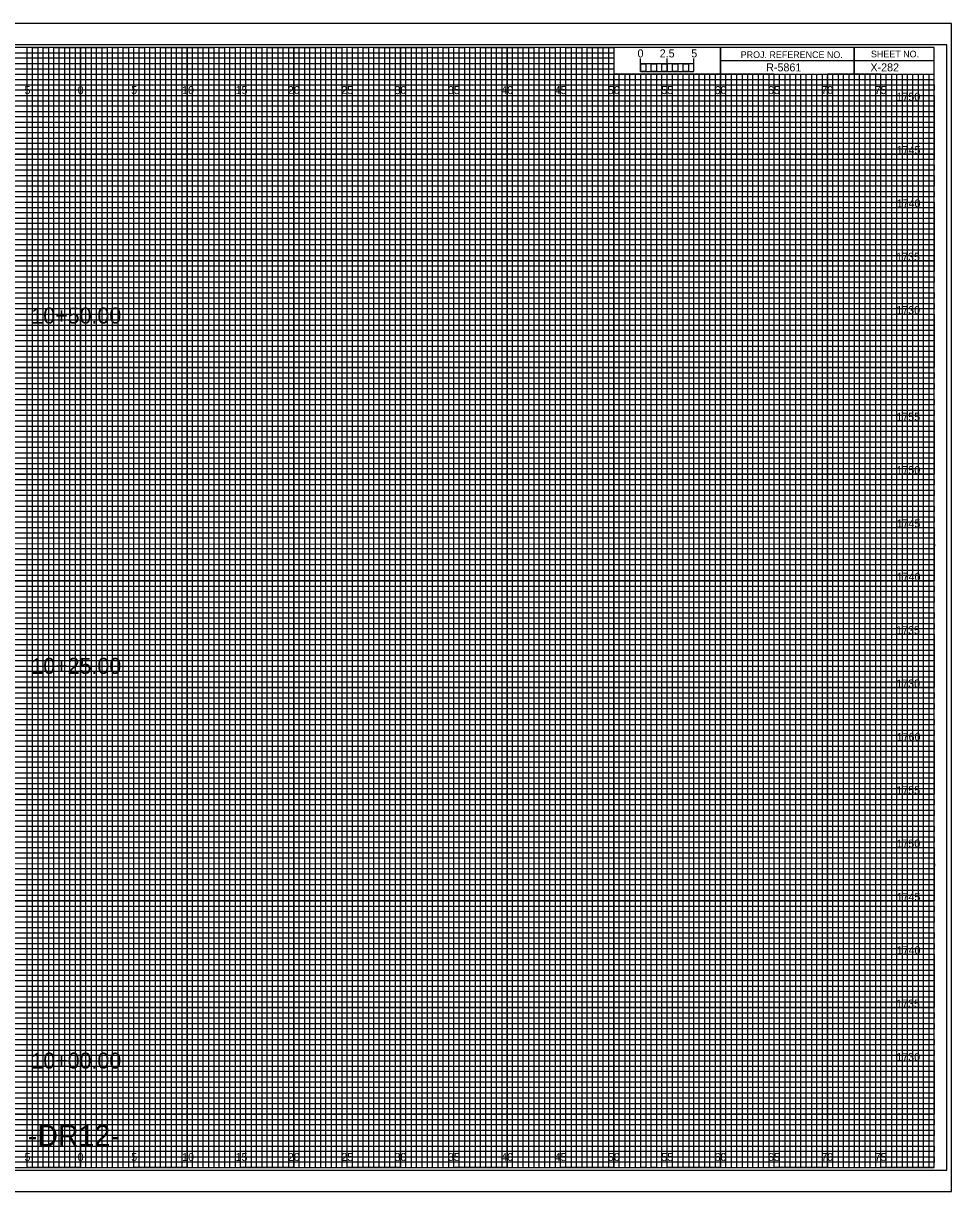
# Model space of a CAD drawing. Extents: x -7 to 162, y -2 to 327.
# Drawn here: x 74.6 to 161.7, y -2.3 to 107.3 of the extents above; entities that cross this region are included whole.
import ezdxf

# ---------------------------------------------------------------- set-up
doc = ezdxf.new("R2010")
doc.units = 0
for name, color, linetype in [('Prop XS Alignment Label', 7, 'Continuous'), ('Prop XS Bar Scale Labels', 7, 'Continuous'), ('Prop XS Elevation Labels', 7, 'Continuous'), ('Prop XS Offset Labels', 7, 'Continuous'), ('Prop XS Project Number', 7, 'Continuous'), ('Prop XS Sheet Number', 7, 'Continuous'), ('Prop XS Station Labels', 7, 'Continuous'), ('Sheet Cross Section CELL', 7, 'Continuous'), ('Sheet Cross Section Grid Major CELL', 7, 'Continuous'), ('Sheet Cross Section Grid Middle CELL', 7, 'Continuous'), ('Sheet Cross Section Grid Minor 1 CELL', 7, 'Continuous'), ('Sheet Cross Section Grid Minor 2 CELL', 7, 'Continuous'), ('Sheet Cross Section Scale CELL', 7, 'Continuous'), ('Sheet Cutting Line CELL', 7, 'Continuous'), ('Sheet DOT Grid CELL', 7, 'Continuous'), ('Sheet Plot Border Inside CELL', 7, 'Continuous'), ('Sheet Plot Border Outside CELL', 7, 'Continuous')]:
    doc.layers.add(name, color=color, linetype=linetype)

msp = doc.modelspace()

# ---------------------------------------------------------------- linework, layer by layer
at = {"layer": 'Sheet Cross Section CELL'}
for p, q in [((152.5, 105), (152.5, 102.5)), ((152.5, 102.5), (152.5, 105)), ((160, 103.75), (140, 103.75)), ((140, 103.75), (140, 102.5)), ((140, 102.5), (160, 102.5))]:
    msp.add_line(p, q, dxfattribs=at)
for points in [[(160, 105), (0, 105), (0, 0), (160, 0)], [(140, 105), (130, 105), (130, 102.52), (140, 102.52)], [(160, 105), (140, 105), (140, 102.5), (160, 102.5)]]:
    msp.add_lwpolyline(points, close=True, dxfattribs=at)
at = {"layer": 'Sheet Cross Section Grid Major CELL'}
for p, q in [((75, 105), (70, 105)), ((75, 0), (75, 105)), ((85, 105), (80, 105)), ((80, 105), (80, 0)), ((85, 0), (85, 105)), ((95, 105), (90, 105)), ((90, 105), (90, 0)), ((95, 0), (95, 105)), ((105, 105), (100, 105)), ((100, 105), (100, 0)), ((105, 0), (105, 105)), ((115, 105), (110, 105)), ((110, 105), (110, 0)), ((115, 0), (115, 105)), ((125, 105), (120, 105)), ((120, 105), (120, 0)), ((125, 0), (125, 105)), ((130, 105), (130, 0)), ((135, 0), (135, 102.5)), ((145, 102.5), (140, 102.5)), ((140, 102.5), (140, 0)), ((145, 0), (145, 102.5)), ((155, 102.5), (150, 102.5)), ((150, 102.5), (150, 0)), ((155, 0), (155, 102.5)), ((80, 0), (75, 0)), ((90, 0), (85, 0)), ((100, 0), (95, 0)), ((110, 0), (105, 0)), ((120, 0), (115, 0)), ((130, 0), (125, 0)), ((140, 0), (135, 0)), ((150, 0), (145, 0)), ((160, 0), (155, 0)), ((160, 0), (160, 0))]:
    msp.add_line(p, q, dxfattribs=at)
for points in [[(0, 100), (160, 100), (160, 95), (0, 95)], [(0, 90), (160, 90), (160, 85), (0, 85)], [(0, 80), (160, 80), (160, 75), (0, 75)], [(0, 70), (160, 70), (160, 65), (0, 65)], [(0, 60), (160, 60), (160, 55), (0, 55)], [(0, 50), (160, 50), (160, 45), (0, 45)], [(0, 40), (160, 40), (160, 35), (0, 35)], [(0, 30), (160, 30), (160, 25), (0, 25)], [(0, 20), (160, 20), (160, 15), (0, 15)], [(0, 10), (160, 10), (160, 5), (0, 5)]]:
    msp.add_lwpolyline(points, dxfattribs=at)
at = {"layer": 'Sheet Cross Section Grid Middle CELL'}
for points in [[(72.5, 0), (77.5, 0), (77.5, 105), (82.5, 105), (82.5, 0), (87.5, 0), (87.5, 105), (92.5, 105), (92.5, 0), (97.5, 0), (97.5, 105), (102.5, 105), (102.5, 0), (107.5, 0), (107.5, 105), (112.5, 105), (112.5, 0), (117.5, 0), (117.5, 105), (122.5, 105), (122.5, 0), (127.5, 0), (127.5, 105), (129.97, 105), (130, 105), (130, 102.5), (132.5, 102.5), (132.5, 0), (137.5, 0), (137.5, 102.5), (142.5, 102.5), (142.5, 0), (147.5, 0), (147.5, 102.5), (152.5, 102.5), (152.5, 0), (157.5, 0), (157.5, 102.5)], [(0, 102.5), (137.5, 102.5)], [(0, 92.5), (160, 92.5), (160, 97.5), (0, 97.5)], [(0, 82.5), (160, 82.5), (160, 87.5), (0, 87.5)], [(0, 72.5), (160, 72.5), (160, 77.5), (0, 77.5)], [(0, 62.5), (160, 62.5), (160, 67.5), (0, 67.5)], [(0, 52.5), (160, 52.5), (160, 57.5), (0, 57.5)], [(0, 42.5), (160, 42.5), (160, 47.5), (0, 47.5)], [(0, 32.5), (160, 32.5), (160, 37.5), (0, 37.5)], [(0, 22.5), (160, 22.5), (160, 27.5), (0, 27.5)], [(0, 12.5), (160, 12.5), (160, 17.5), (0, 17.5)], [(0, 2.5), (160, 2.5), (160, 7.5), (0, 7.5)]]:
    msp.add_lwpolyline(points, dxfattribs=at)
at = {"layer": 'Sheet Cross Section Grid Minor 1 CELL'}
for p, q in [((0, 104.5), (130, 104.5)), ((130, 104.5), (130, 103.99)), ((130, 103.99), (0, 103.99)), ((0, 103.5), (130, 103.5)), ((130, 102.95), (0, 102.95)), ((130, 103.5), (130, 102.95)), ((0, 102), (160, 102))]:
    msp.add_line(p, q, dxfattribs=at)
for points in [[(0, 101.5), (135, 101.5), (160, 101.5), (160, 101), (0, 101)], [(0, 100.5), (160, 100.5), (160, 99.5), (0, 99.5)], [(0, 99), (160, 99), (160, 98.5), (0, 98.49)], [(0, 98), (160, 98), (160, 97), (0, 97)], [(0, 96.5), (160, 96.5), (160, 96), (0, 96)], [(0, 95.5), (160, 95.5), (160, 94.5), (0, 94.5)], [(0, 94), (160, 94), (160, 93.5), (0, 93.5)], [(0, 93), (160, 93), (160, 92), (0, 92)], [(0, 91.5), (160, 91.5), (160, 91), (0, 91)], [(0, 90.5), (160, 90.5), (160, 89.5), (0, 89.5)], [(0, 89), (160, 89), (160, 88.5), (0, 88.5)], [(0, 88), (160, 88), (160, 86.98), (160, 86.5), (160, 86), (0, 86)], [(0, 87), (160, 87), (160, 86.5), (0, 86.5)], [(0, 85.5), (160, 85.5), (160, 84.5), (0, 84.52)], [(0, 84.52), (160, 84.5), (160, 84), (0, 84)], [(0, 83.5), (160, 83.5), (160, 83), (0, 83)], [(0, 82), (160, 82), (160, 81.5), (0, 81.5)], [(0, 81), (160, 81), (160, 80.5), (0, 80.5)], [(-0.04, 79.45), (160, 79.45), (160, 78.94), (-0.04, 78.94)], [(0, 78.5), (160, 78.5), (160, 78), (0, 78)], [(0, 77), (160, 77), (160, 76.5), (0, 76.5)], [(0, 76), (160, 76), (160, 75.5), (0, 75.5)], [(0, 74.5), (160, 74.5), (160, 74), (0, 74)], [(0, 73.5), (160, 73.5), (160, 73), (0, 73)], [(0, 72), (160, 72), (160, 71.5), (0, 71.5)], [(0, 71), (160, 71), (160, 70.5), (0, 70.5)], [(0, 69.5), (160, 69.5), (160, 68.99), (0, 69)], [(0, 68.5), (160, 68.5), (160, 68), (0, 68)], [(0, 67), (160, 67), (160, 66.5), (0, 66.5)], [(0, 66), (160, 66), (160, 65.5), (0, 65.5)], [(0, 64.5), (160, 64.5), (160, 64), (0, 64)], [(0, 63.5), (160, 63.5), (160, 63), (0, 63)], [(0, 62), (160, 62), (160, 61.5), (0, 61.5)], [(0, 61), (160, 61), (160, 60.5), (0, 60.5)], [(0, 59.5), (160, 59.5), (160, 59), (0, 59)], [(0, 58.5), (160.03, 58.45), (160, 58), (0, 58)], [(0, 57), (160, 57), (160, 56.5), (0, 56.5)], [(0, 56), (160, 56), (160, 55.5), (0, 55.5)], [(0, 54.5), (160, 54.5), (160, 54), (0, 54)], [(0, 53.5), (160, 53.5), (160, 53), (0, 53)], [(0, 52), (160, 52), (160, 51.5), (0, 51.5)], [(0, 51), (160, 51), (160, 50.5), (0, 50.5)], [(0, 49.5), (160, 49.5), (160, 49), (0, 49)], [(0, 48.5), (160, 48.5), (160, 48), (0, 48)], [(0, 47), (160, 47), (160, 46.5), (0, 46.5)], [(0, 46), (160, 46), (160, 45.5), (0, 45.5)], [(0, 44.5), (160, 44.5), (160, 44), (0, 44)], [(0, 43.5), (160, 43.5), (160, 43), (0, 43)], [(0, 42), (160, 42), (160, 41.5), (0, 41.5)], [(0, 41), (160, 41), (160, 40.5), (0, 40.5)], [(0, 39.5), (160, 39.5), (160, 38.99), (0, 39)], [(0, 38.5), (160, 38.5), (160, 38), (0, 38)], [(0, 37), (160, 37), (160, 36.5), (0, 36.5)], [(0, 36), (160, 36), (160, 35.5), (0, 35.5)], [(0, 34.5), (160, 34.5), (160, 34), (0, 34)], [(0, 33.5), (160, 33.5), (160, 33), (0, 33)], [(0, 32), (160, 32), (160, 31.5), (0, 31.5)], [(0, 31), (160, 31), (160, 30.5), (0, 30.5)], [(0, 29.5), (160, 29.5), (160, 29), (0, 29)], [(0, 28.5), (160.03, 28.46), (160, 28), (0, 28)], [(0, 27), (160, 27), (160, 26.5), (0, 26.5)], [(0, 26), (160, 26), (160, 25.5), (0, 25.5)], [(0, 24.5), (160, 24.5), (160, 24), (0, 24)], [(0, 23.5), (160, 23.5), (160, 23), (0, 23)], [(0, 22), (160, 22), (160, 21.5), (0, 21.5)], [(0, 21), (160, 21), (160, 20.5), (0, 20.5)], [(0, 19.5), (160, 19.5), (160, 19), (0, 19)], [(0, 18.5), (160, 18.5), (160, 18), (0, 18)], [(0, 17), (160, 17), (160, 16.5), (0, 16.5)], [(0, 16), (160, 16), (160, 15.5), (0, 15.5)], [(0, 14.5), (160, 14.5), (160, 14), (0, 14)], [(0, 13.5), (160, 13.5), (160, 13), (0, 13)], [(0, 12), (160, 12), (160, 11.5), (0, 11.5)], [(0, 11), (160, 11), (160, 10.5), (0, 10.5)], [(0, 9.5), (160, 9.5), (160, 9), (0, 9)], [(0, 8.5), (160, 8.5), (160, 8), (0, 8)], [(0, 7), (160, 7), (160, 6.5), (0, 6.5)], [(0, 6), (160, 6), (160, 5.5), (0, 5.5)], [(0, 4.5), (160, 4.5), (160, 4), (0, 4)], [(0, 3.5), (160, 3.5), (160, 3), (0, 3)], [(0, 2), (160, 2), (160, 1.5), (0, 1.5)], [(0, 1), (160, 1), (160, 0.5), (0, 0.5)]]:
    msp.add_lwpolyline(points, dxfattribs=at)
at = {"layer": 'Sheet Cross Section Grid Minor 2 CELL'}
for p, q in [((133.5, 102.5), (133, 102.5)), ((133, 102.5), (133, 0)), ((133.5, 0), (133.5, 102.5)), ((134.5, 102.5), (134, 102.5)), ((134, 102.5), (134, 0)), ((134.5, 0), (134.5, 102.5)), ((133, 0), (132.5, 0)), ((134, 0), (133.5, 0))]:
    msp.add_line(p, q, dxfattribs=at)
for points in [[(75, 0), (75.5, 0), (75.5, 105), (76, 105), (76, 0)], [(76, 0), (76.5, 0), (76.5, 105), (77, 105), (77, 0)], [(77.5, 0), (78, 0), (78, 105), (78.5, 105), (78.5, 0)], [(78.5, 0), (79, 0), (79, 105), (79.5, 105), (79.5, 0)], [(80, 0), (80.5, 0), (80.5, 105), (81, 105), (81, 0)], [(81, 0), (81.5, 0), (81.5, 105), (82, 105), (82, 0)], [(82.5, 0), (83, 0), (83, 105), (83.5, 105), (83.5, 0)], [(83.5, 0), (84, 0), (84, 105), (84.5, 105), (84.5, 0)], [(85, 0), (85.5, 0), (85.5, 105), (86, 105), (86, 0)], [(86, 0), (86.5, 0), (86.5, 105), (87, 105), (87, 0)], [(87.5, 0), (88, 0), (88, 105), (88.5, 105), (88.5, 0)], [(88.5, 0), (89, 0), (89, 105), (89.5, 105), (89.5, 0)], [(90, 0), (90.5, 0), (90.5, 105), (91, 105), (91, 0)], [(91, 0), (91.5, 0), (91.5, 105), (92, 105), (92, 0)], [(92.5, 0), (93, 0), (93, 105), (93.5, 105), (93.5, 0)], [(93.5, 0), (94, 0), (94, 105), (94.5, 105), (94.5, 0)], [(95, 0), (95.5, 0), (95.5, 105), (96, 105), (96, 0)], [(96, 0), (96.5, 0), (96.5, 105), (97, 105), (97, 0)], [(97.5, 0), (98, 0), (98, 105), (98.5, 105), (98.5, 0)], [(98.5, 0), (99, 0), (99, 105), (99.5, 105), (99.5, 0)], [(100, 0), (100.5, 0), (100.5, 105), (101, 105), (101, 0)], [(101, 0), (101.5, 0), (101.5, 105), (102, 105), (102, 0)], [(102.5, 0), (103, 0), (103, 105), (103.5, 105), (103.5, 0)], [(103.5, 0), (104, 0), (104, 105), (104.5, 105), (104.5, 0)], [(105, 0), (105.5, 0), (105.5, 105), (106, 105), (106, 0)], [(106, 0), (106.5, 0), (106.5, 105), (107, 105), (107, 0)], [(107.5, 0), (108, 0), (108, 105), (108.5, 105), (108.5, 0)], [(108.5, 0), (109, 0), (109, 105), (109.5, 105), (109.5, 0)], [(110, 0), (110.5, 0), (110.5, 105), (111, 105), (111, 0)], [(111, 0), (111.5, 0), (111.5, 105), (112, 105), (112, 0)], [(112.5, 0), (113, 0), (113, 105), (113.5, 105), (113.5, 0)], [(113.5, 0), (114, 0), (114, 105), (114.5, 105), (114.5, 0)], [(115, 0), (115.5, 0), (115.5, 105), (116, 105), (116, 0)], [(116, 0), (116.5, 0), (116.5, 105), (117, 105), (117, 0)], [(117.5, 0), (118, 0), (118, 105), (118.5, 105), (118.5, 0)], [(118.5, 0), (119, 0), (119, 105), (119.5, 105), (119.5, 0)], [(120, 0), (120.5, 0), (120.5, 105), (121, 105), (121, 0)], [(121, 0), (121.5, 0), (121.5, 105), (122, 105), (122, 0)], [(122.5, 0), (123, 0), (123, 105), (123.5, 105), (123.5, 0)], [(123.5, 0), (124, 0), (124, 105), (124.5, 105), (124.5, 0)], [(125, 0), (125.5, 0), (125.5, 105), (126, 105), (126, 0)], [(126, 0), (126.5, 0), (126.5, 105), (127, 105), (127, 0)], [(127.5, 0), (128, 0), (128, 105), (128.5, 105), (128.5, 0)], [(128.5, 0), (129, 0), (129, 105), (129.5, 105), (129.5, 0)], [(130, 0), (130.5, 0), (130.5, 102.5), (131.01, 102.5), (131.01, 0)], [(131, 0), (131.5, 0), (131.5, 102.5), (132, 102.5), (132, 0)], [(135, 0), (135.49, 0), (135.49, 102.5), (136, 102.5), (136, 0)], [(136, 0), (136.5, 0), (136.5, 102.5), (137.03, 102.5), (137.03, 0)], [(137.5, 0), (138, 0), (138, 102.5), (138.5, 102.5), (138.5, 0)], [(138.5, 0), (139, 0), (139, 102.5), (139.5, 102.5), (139.5, 0)], [(140, 0), (140.5, 0), (140.5, 102.5), (141, 102.5), (141, 0)], [(141, 0), (141.5, 0), (141.5, 102.5), (142, 102.5), (142, 0)], [(142.5, 0), (143, 0), (143, 102.5), (143.5, 102.5), (143.5, 0)], [(143.5, 0), (144, 0), (144, 102.5), (144.5, 102.5), (144.5, 0)], [(145, 0), (145.5, 0), (145.5, 102.5), (146, 102.5), (146, 0)], [(146, 0), (146.5, 0), (146.5, 102.5), (147, 102.5), (147, 0)], [(147.5, 0), (148, 0), (148, 102.5), (148.5, 102.5), (148.5, 0)], [(148.5, 0), (149, 0), (149, 102.5), (149.5, 102.5), (149.5, 0)], [(150, 0), (150.5, 0), (150.5, 102.5), (151, 102.5), (151, 0)], [(151, 0), (151.5, 0), (151.5, 102.5), (152, 102.5), (152, 0)], [(152.5, 0), (153, 0), (153, 102.5), (153.5, 102.5), (153.5, 0)], [(153.5, 0), (154, 0), (154, 102.5), (154.5, 102.5), (154.5, 0)], [(155, 0), (155.5, 0), (155.5, 102.5), (156, 102.5), (156, 0)], [(156, 0), (156.5, 0), (156.5, 102.5), (157, 102.5), (157, 0)], [(157.5, 0), (158, 0), (158, 102.5), (158.5, 102.5), (158.5, 0)], [(158.5, 0), (159, 0), (159, 102.5), (159.5, 102.5), (159.5, 0)]]:
    msp.add_lwpolyline(points, dxfattribs=at)
at = {"layer": 'Sheet Cross Section Scale CELL'}
for p, q in [((132.5, 102.75), (132.5, 103.95)), ((132.5, 103.45), (132.5, 103.95)), ((135, 102.75), (135, 103.95)), ((137.5, 102.75), (137.5, 103.95)), ((137.5, 103.45), (137.5, 103.95))]:
    msp.add_line(p, q, dxfattribs=at)
for points in [[(137.5, 103.45), (132.5, 103.45), (132.5, 102.75), (137.5, 102.75)], [(132.5, 103.45), (133, 103.45), (133, 102.75), (132.5, 102.75)], [(133.5, 103.45), (134, 103.45), (134, 102.75), (133.5, 102.75)], [(134.5, 103.45), (135, 103.45), (135, 102.75), (134.5, 102.75)], [(135.5, 103.45), (136, 103.45), (136, 102.75), (135.5, 102.75)], [(136.5, 103.45), (137, 103.45), (137, 102.75), (136.5, 102.75)]]:
    msp.add_lwpolyline(points, close=True, dxfattribs=at)
at = {"layer": 'Sheet Cutting Line CELL'}
for p, q in [((161.65, 107.25), (-6.7, 107.25)), ((-6.7, -2.25), (161.65, -2.25))]:
    msp.add_line(p, q, dxfattribs=at)
at = {"layer": 'Sheet DOT Grid CELL'}
for p, q in [((75, 0), (75, 105)), ((80, 0), (80, 105)), ((85, 0), (85, 105)), ((90, 0), (90, 105)), ((95, 0), (95, 105)), ((100, 0), (100, 105)), ((105, 0), (105, 105)), ((110, 0), (110, 105)), ((115, 0), (115, 105)), ((120, 0), (120, 105)), ((125, 0), (125, 105)), ((130, 0), (130, 102.34)), ((135, 0), (135, 102.34)), ((140, 0), (140, 102.34)), ((145, 0), (145, 102.34)), ((150, 0), (150, 102.34)), ((155, 0), (155, 102.34)), ((0, 100), (160, 100)), ((0, 95), (160, 95)), ((0, 90), (160, 90)), ((0, 85), (160, 85)), ((0, 80), (160, 80)), ((0, 75), (160, 75)), ((0, 70), (160, 70)), ((0, 65), (160, 65)), ((0, 60), (160, 60)), ((0, 55), (160, 55)), ((0, 50), (160, 50)), ((0, 45), (160, 45)), ((0, 40), (160, 40)), ((0, 35), (160, 35)), ((0, 30), (160, 30)), ((0, 25), (160, 25)), ((0, 20), (160, 20)), ((0, 15), (160, 15)), ((0, 10), (160, 10)), ((0, 5), (160, 5))]:
    msp.add_line(p, q, dxfattribs=at)
at = {"layer": 'Sheet Plot Border Inside CELL'}
msp.add_lwpolyline([(-5.4, -0.25), (161.2, -0.25), (161.2, 105.25), (-5.4, 105.25)], close=True, dxfattribs=at)
at = {"layer": 'Sheet Plot Border Outside CELL'}
msp.add_lwpolyline([(-6.7, -2.25), (161.65, -2.25), (161.65, 107.25), (-6.7, 107.25)], close=True, dxfattribs=at)

# ---------------------------------------------------------------- texts
at = {"layer": 'Prop XS Alignment Label'}
msp.add_text('-DR12-', height=2, dxfattribs=at).set_placement((75.06, 2))
at = {"layer": 'Prop XS Bar Scale Labels'}
for s, p in [('2.5', (134.29, 104.06)), ('5', (137.24, 104.06))]:
    msp.add_text(s, height=0.75, dxfattribs=at).set_placement(p)
at = {"layer": 'Prop XS Elevation Labels'}
for s, p in [('1750', (156.48, 100)), ('1745', (156.49, 95)), ('1740', (156.5, 90)), ('1735', (156.45, 85)), ('1730', (156.46, 80)), ('1755', (156.47, 70)), ('1750', (156.48, 65)), ('1745', (156.49, 60)), ('1740', (156.5, 55)), ('1735', (156.45, 50)), ('1730', (156.46, 45)), ('1760', (156.5, 40)), ('1755', (156.47, 35)), ('1750', (156.48, 30)), ('1745', (156.49, 25)), ('1740', (156.5, 20)), ('1735', (156.45, 15)), ('1730', (156.46, 10))]:
    msp.add_text(s, height=0.75, dxfattribs=at).set_placement(p)
at = {"layer": 'Prop XS Offset Labels'}
for s, p in [('5', (74.74, 100.62)), ('0', (79.73, 100.62)), ('0', (79.73, 100.62)), ('5', (84.74, 100.62)), ('10', (89.52, 100.62)), ('15', (94.53, 100.62)), ('20', (99.43, 100.62)), ('25', (104.44, 100.62)), ('30', (109.43, 100.62)), ('35', (114.44, 100.62)), ('40', (119.43, 100.62)), ('45', (124.44, 100.62)), ('50', (129.43, 100.62)), ('55', (134.44, 100.62)), ('60', (139.43, 100.62)), ('65', (144.44, 100.62)), ('70', (149.43, 100.62)), ('75', (154.44, 100.62)), ('5', (74.74, 0.62)), ('0', (79.73, 0.62)), ('0', (79.73, 0.62)), ('5', (84.74, 0.62)), ('10', (89.52, 0.62)), ('15', (94.53, 0.62)), ('20', (99.43, 0.62)), ('25', (104.44, 0.62)), ('30', (109.43, 0.62)), ('35', (114.44, 0.62)), ('40', (119.43, 0.62)), ('45', (124.44, 0.62)), ('50', (129.43, 0.62)), ('55', (134.44, 0.62)), ('60', (139.43, 0.62)), ('65', (144.44, 0.62)), ('70', (149.43, 0.62)), ('75', (154.44, 0.62))]:
    msp.add_text(s, height=0.75, dxfattribs=at).set_placement(p)
at = {"layer": 'Prop XS Project Number'}
msp.add_text('R-5861', height=0.75, dxfattribs=at).set_placement((144.27, 102.75))
at = {"layer": 'Prop XS Sheet Number'}
msp.add_text('X-282', height=0.75, dxfattribs=at).set_placement((154.04, 102.75))
at = {"layer": 'Prop XS Station Labels'}
for s, p in [('10+50.00', (75.39, 79.11)), ('10+25.00', (75.39, 46.28)), ('10+00.00', (75.39, 9.28))]:
    msp.add_text(s, height=1.5, dxfattribs=at).set_placement(p)
at = {"layer": 'Sheet Cross Section CELL'}
for s, p in [('PROJ. REFERENCE NO.', (141.88, 104)), ('SHEET NO.', (154.09, 104.06))]:
    msp.add_text(s, height=0.625, dxfattribs=at).set_placement(p)
at = {"layer": 'Sheet Cross Section Scale CELL'}
msp.add_text('0', height=0.75, dxfattribs=at).set_placement((132.21, 104.06))

doc.saveas('drawing.dxf')
